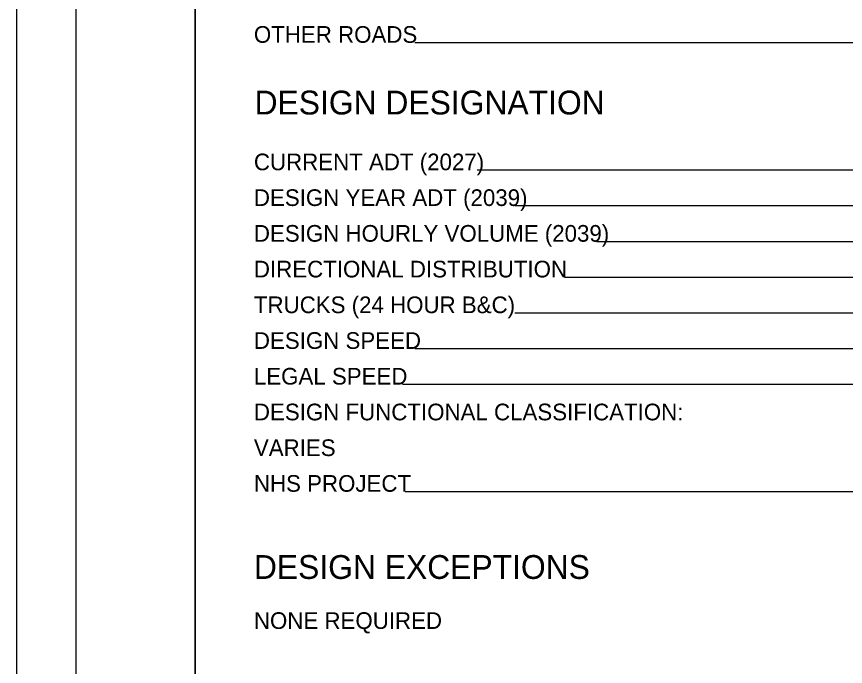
# Model space of a CAD drawing. Extents: x 0 to 34, y 0 to 22.
# Drawn here: x 0 to 6.97, y 5.64 to 11.1 of the extents above; entities that cross this region are included whole.
import ezdxf

# ---------------------------------------------------------------- set-up
doc = ezdxf.new("R2010")
doc.units = 0
for name, color, linetype in [('SH_Border', 7, 'Continuous'), ('SH_Cut_Line', 7, 'Continuous'), ('SH_Data', 7, 'Continuous'), ('SH_Text', 7, 'Continuous')]:
    doc.layers.add(name, color=color, linetype=linetype)

msp = doc.modelspace()

# ---------------------------------------------------------------- linework, layer by layer
at = {"layer": 'SH_Border'}
for points in [[(0.5, 21.5), (1.5, 21.5), (1.5, 0.5), (0.5, 0.5)], [(1.5, 21.5), (33.5, 21.5), (33.5, 0.5), (1.5, 0.5)]]:
    msp.add_lwpolyline(points, close=True, dxfattribs=at)
at = {"layer": 'SH_Cut_Line'}
msp.add_lwpolyline([(0, 0), (34, 0), (34, 22), (0, 22)], close=True, dxfattribs=at)
at = {"layer": 'SH_Data'}
for p, q in [((7.7, 10.8767), (3.3471, 10.8767)), ((7.6424, 9.8062), (3.871, 9.8062)), ((7.6368, 9.5062), (4.1885, 9.5062)), ((7.6368, 9.2062), (4.8723, 9.2062)), ((7.6368, 8.9062), (4.6037, 8.9062)), ((7.6368, 8.6062), (4.1885, 8.6062)), ((7.6368, 8.3062), (3.346, 8.3062)), ((7.6368, 8.0062), (3.2422, 8.0062)), ((7.6368, 7.1062), (3.2669, 7.1062))]:
    msp.add_line(p, q, dxfattribs=at)

# ---------------------------------------------------------------- texts
msp.add_text('DESIGN DESIGNATION', height=0.2, dxfattribs=at).set_placement((2, 10.2747))
at = {"layer": 'SH_Text'}
for s, height, p in [('OTHER ROADS', 0.14, (1.9944, 10.8767)), ('CURRENT ADT (2027)', 0.14, (1.9944, 9.8062)), ('DESIGN YEAR ADT (2039)', 0.14, (1.9944, 9.5062)), ('DESIGN HOURLY VOLUME (2039)', 0.14, (1.9944, 9.2062)), ('DIRECTIONAL DISTRIBUTION', 0.14, (1.9944, 8.9062)), ('TRUCKS (24 HOUR B&C)', 0.14, (1.9944, 8.6062)), ('DESIGN SPEED', 0.14, (1.9944, 8.3062)), ('LEGAL SPEED', 0.14, (1.9944, 8.0062)), ('DESIGN FUNCTIONAL CLASSIFICATION:', 0.14, (1.9944, 7.7062)), ('VARIES', 0.14, (1.9944, 7.4062)), ('NHS PROJECT', 0.14, (1.9944, 7.1062)), ('DESIGN EXCEPTIONS', 0.2, (1.9944, 6.3744)), ('NONE REQUIRED', 0.14, (1.9944, 5.9544))]:
    msp.add_text(s, height=height, dxfattribs=at).set_placement(p)

doc.saveas('drawing.dxf')
